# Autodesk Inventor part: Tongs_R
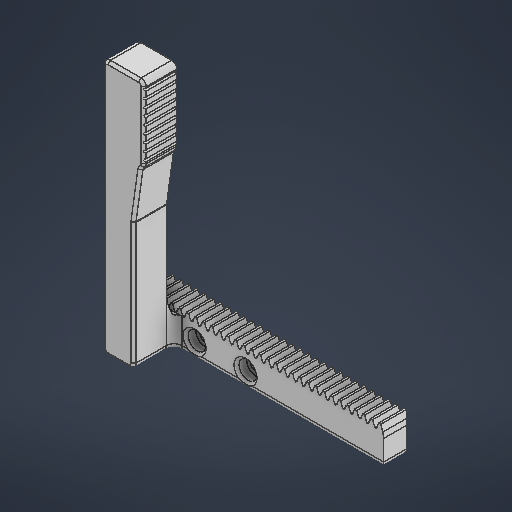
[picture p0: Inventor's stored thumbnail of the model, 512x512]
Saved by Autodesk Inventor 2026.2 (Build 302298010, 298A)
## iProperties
Company: Open CASCADE
Created: 2026-05
Part Number: Tongs_R
Material: 일반
Description: Open CASCADE Model
Document SubType Name: Modeling
Designer: work
Authority: Unknown
Density: 1 g/cm^3
Appearance: 기본값
Sending System: Open CASCADE 7.8
Preprocessor: Open CASCADE STEP processor 7.8
Title: Open CASCADE Shape Model
Author: Author
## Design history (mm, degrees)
feature "기준1"
sketch "스케치1"
  geometry: L1 (0.33, 2)-(1.149, 4.25) reference; L2 (0, 0)-(0.33, 2) reference; L3 (94.248, 0)-(0, 0) reference; L4 (93.917, 2)-(94.248, 0) reference; L5 (93.098, 4.25)-(93.917, 2) reference; L6 (92.256, 4.25)-(93.098, 4.25) reference; L7 (91.437, 2)-(92.256, 4.25) reference; L8 (90.776, 2)-(91.437, 2) reference; L9 (89.957, 4.25)-(90.776, 2) reference; L10 (89.114, 4.25)-(89.957, 4.25) reference; L11 (88.295, 2)-(89.114, 4.25) reference; L12 (87.634, 2)-(88.295, 2) reference; L13 (86.815, 4.25)-(87.634, 2) reference; L14 (85.972, 4.25)-(86.815, 4.25) reference; L15 (85.153, 2)-(85.972, 4.25) reference; L16 (84.493, 2)-(85.153, 2) reference; L17 (83.674, 4.25)-(84.493, 2) reference; L18 (82.831, 4.25)-(83.674, 4.25) reference; L19 (82.012, 2)-(82.831, 4.25) reference; L20 (81.351, 2)-(82.012, 2) reference; L21 (80.532, 4.25)-(81.351, 2) reference; L22 (79.689, 4.25)-(80.532, 4.25) reference; L23 (78.87, 2)-(79.689, 4.25) reference; L24 (78.209, 2)-(78.87, 2) reference; L25 (77.39, 4.25)-(78.209, 2) reference; L26 (76.548, 4.25)-(77.39, 4.25) reference; L27 (75.729, 2)-(76.548, 4.25) reference; L28 (75.068, 2)-(75.729, 2) reference; L29 (74.249, 4.25)-(75.068, 2) reference; L30 (73.406, 4.25)-(74.249, 4.25) reference; L31 (72.587, 2)-(73.406, 4.25) reference; L32 (71.926, 2)-(72.587, 2) reference; L33 (71.107, 4.25)-(71.926, 2) reference; L34 (70.264, 4.25)-(71.107, 4.25) reference; L35 (69.445, 2)-(70.264, 4.25) reference; L36 (68.785, 2)-(69.445, 2) reference; L37 (67.966, 4.25)-(68.785, 2) reference; L38 (67.123, 4.25)-(67.966, 4.25) reference; L39 (66.304, 2)-(67.123, 4.25) reference; L40 (65.643, 2)-(66.304, 2) reference; L41 (64.824, 4.25)-(65.643, 2) reference; L42 (63.981, 4.25)-(64.824, 4.25) reference; L43 (63.162, 2)-(63.981, 4.25) reference; L44 (62.501, 2)-(63.162, 2) reference; L45 (61.682, 4.25)-(62.501, 2) reference; L46 (60.84, 4.25)-(61.682, 4.25) reference; L47 (60.021, 2)-(60.84, 4.25) reference; L48 (59.36, 2)-(60.021, 2) reference; L49 (58.541, 4.25)-(59.36, 2) reference; L50 (57.698, 4.25)-(58.541, 4.25) reference; L51 (56.879, 2)-(57.698, 4.25) reference; L52 (56.218, 2)-(56.879, 2) reference; L53 (55.399, 4.25)-(56.218, 2) reference; L54 (54.556, 4.25)-(55.399, 4.25) reference; L55 (53.738, 2)-(54.556, 4.25) reference; L56 (53.077, 2)-(53.738, 2) reference; L57 (52.258, 4.25)-(53.077, 2) reference; L58 (51.415, 4.25)-(52.258, 4.25) reference; L59 (50.596, 2)-(51.415, 4.25) reference; L60 (49.935, 2)-(50.596, 2) reference; L61 (49.116, 4.25)-(49.935, 2) reference; L62 (48.273, 4.25)-(49.116, 4.25) reference; L63 (47.454, 2)-(48.273, 4.25) reference; L64 (46.793, 2)-(47.454, 2) reference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; 1 further point
  constraints: 8 end point, 2 parallel, 1 horizontal, 1 perpendicular, 1 point on line
  dimensions: "d0" = 10 distance of L123.end L124.end
extrude "돌출1" join sketch "스케치1" stored distance "d1" = 10; taper "d2" = 0 deg
sketch "스케치2"
  geometry: L1 (0.33, 12)-(1.149, 14.25) reference; L2 (0, 10)-(0.33, 12) reference; L3 (0, 10)-(0, 0) reference; L4 (0, 0)-(94.248, 0) reference; L5 (94.248, 0)-(94.248, 10) reference; L6 (93.917, 12)-(94.248, 10) reference; L7 (93.098, 14.25)-(93.917, 12) reference; L8 (92.256, 14.25)-(93.098, 14.25) reference; L9 (91.437, 12)-(92.256, 14.25) reference; L10 (90.776, 12)-(91.437, 12) reference; L11 (89.957, 14.25)-(90.776, 12) reference; L12 (89.114, 14.25)-(89.957, 14.25) reference; L13 (88.295, 12)-(89.114, 14.25) reference; L14 (87.634, 12)-(88.295, 12) reference; L15 (86.815, 14.25)-(87.634, 12) reference; L16 (85.972, 14.25)-(86.815, 14.25) reference; L17 (85.153, 12)-(85.972, 14.25) reference; L18 (84.493, 12)-(85.153, 12) reference; L19 (83.674, 14.25)-(84.493, 12) reference; L20 (82.831, 14.25)-(83.674, 14.25) reference; L21 (82.012, 12)-(82.831, 14.25) reference; L22 (81.351, 12)-(82.012, 12) reference; L23 (80.532, 14.25)-(81.351, 12) reference; L24 (79.689, 14.25)-(80.532, 14.25) reference; L25 (78.87, 12)-(79.689, 14.25) reference; L26 (78.209, 12)-(78.87, 12) reference; L27 (77.39, 14.25)-(78.209, 12) reference; L28 (76.548, 14.25)-(77.39, 14.25) reference; L29 (75.729, 12)-(76.548, 14.25) reference; L30 (75.068, 12)-(75.729, 12) reference; L31 (74.249, 14.25)-(75.068, 12) reference; L32 (73.406, 14.25)-(74.249, 14.25) reference; L33 (72.587, 12)-(73.406, 14.25) reference; L34 (71.926, 12)-(72.587, 12) reference; L35 (71.107, 14.25)-(71.926, 12) reference; L36 (70.264, 14.25)-(71.107, 14.25) reference; L37 (69.445, 12)-(70.264, 14.25) reference; L38 (68.785, 12)-(69.445, 12) reference; L39 (67.966, 14.25)-(68.785, 12) reference; L40 (67.123, 14.25)-(67.966, 14.25) reference; L41 (66.304, 12)-(67.123, 14.25) reference; L42 (65.643, 12)-(66.304, 12) reference; L43 (64.824, 14.25)-(65.643, 12) reference; L44 (63.981, 14.25)-(64.824, 14.25) reference; L45 (63.162, 12)-(63.981, 14.25) reference; L46 (62.501, 12)-(63.162, 12) reference; L47 (61.682, 14.25)-(62.501, 12) reference; L48 (60.84, 14.25)-(61.682, 14.25) reference; L49 (60.021, 12)-(60.84, 14.25) reference; L50 (59.36, 12)-(60.021, 12) reference; L51 (58.541, 14.25)-(59.36, 12) reference; L52 (57.698, 14.25)-(58.541, 14.25) reference; L53 (56.879, 12)-(57.698, 14.25) reference; L54 (56.218, 12)-(56.879, 12) reference; L55 (55.399, 14.25)-(56.218, 12) reference; L56 (54.556, 14.25)-(55.399, 14.25) reference; L57 (53.738, 12)-(54.556, 14.25) reference; L58 (53.077, 12)-(53.738, 12) reference; L59 (52.258, 14.25)-(53.077, 12) reference; L60 (51.415, 14.25)-(52.258, 14.25) reference; L61 (50.596, 12)-(51.415, 14.25) reference; L62 (49.935, 12)-(50.596, 12) reference; L63 (49.116, 14.25)-(49.935, 12) reference; L64 (48.273, 14.25)-(49.116, 14.25) reference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; C1 r 2 at (40, 5.688); C2 r 2 at (20, 5.688); 4 further points
  constraints: 8 end point, 5 point on line, 4 perpendicular, 3 midpoint, 2 centre point, 1 horizontal
  dimensions: "d4" = 0.5625 distance of L126.end point (47.124, 13.688); "d5" = 8 distance of point (47.124, 5.688) point (47.124, 13.688); "d6" = 4 diameter of C1; "d7" = 4 diameter of C2; "d8" = 20 distance of C1.centre C2.centre; "d36" = 20 horizontal distance of point (0, 5) C2.centre
extrude "돌출2" cut sketch "스케치2" extent not by distance; stored distance "d10" = 0; taper "d11" = 0 deg
sketch "스케치3"
  geometry: L1 (0, 0)-(94.248, 0) reference; L2 (0, 0)-(12, 0); L3 (12, 0)-(12, 100); L4 (12, 100)-(0, 100); L5 (12, 100)-(16, 100); L6 (16, 70)-(12, 70); L7 (12, 70)-(12, 100); L8 (16, 97)-(0, 97); L9 (12, 70)-(12, 0); C1 r 0.5 at (0, 97); C2 r 0.5 at (16, 97); C3 r 0.5 at (16, 94); C4 r 0.5 at (0, 94); C5 r 0.5 at (16, 91); C6 r 0.5 at (0, 91); C7 r 0.5 at (16, 88); C8 r 0.5 at (0, 88); C9 r 0.5 at (16, 85); C10 r 0.5 at (0, 85); C11 r 0.5 at (16, 82); C12 r 0.5 at (0, 82); C13 r 0.5 at (16, 79); C14 r 0.5 at (0, 79); C15 r 0.5 at (16, 76); C16 r 0.5 at (0, 76); C17 r 0.5 at (16, 73); C18 r 0.5 at (0, 73); 38 further points
  constraints: 18 centre point, 16 end point, 16 equal radius, 16 vertical alignment, 4 horizontal, 3 vertical, 2 parallel, 1 perpendicular, 8 other
  dimensions: "d12" = 12 distance of L3.end L4.end; "d13" = 100 distance between parallel lines of L1 L4; "d14" = 30 distance of L5.end L6.start; "d15" = 4 distance of L6.start L6.end; "d16" = 1 diameter of C1; "d17" = 1 diameter of C2; "d18" = 3 distance between parallel lines of L4 L8; "d21" = 3 distance of L8.start C3.centre
extrude "돌출3" join sketch "스케치3" distance "d26" = 16; taper "d27" = 0 deg
chamfer "모따기1" distance "d28" = 20; stored, may be unused: second distance "d29" = 2, angle "d30" = 171.887 deg
sketch "스케치4"
  geometry: L1 (0, 10)-(0, 0) reference; L2 (0, 0)-(26, 0) reference; L3 (26, 72.5)-(26, 0) reference; L4 (10, 72.5)-(26, 72.5) reference; L5 (10, 72.5)-(10, 10) reference; L6 (0, 10)-(10, 10) reference; L7 (26, 50)-(10, 10) reference; L8 (13, 20)-(13, 100); L9 (10, 100)-(26, 100) reference; L10 (10, 72.5)-(13, 72.5); L11 (13, 72.5)-(13, 100); L12 (13, 100)-(10, 100); L13 (10, 100)-(10, 72.5); A1 r 18.167 centre (-5.167, 20) between (10, 10) and (13, 20); 3 further points
  constraints: 10 end point, 2 parallel, 2 perpendicular, 2 point on circle, 1 centre point, 1 horizontal, 1 midpoint, 1 point on line, 1 tangent
  dimensions: "d31" = 10 vertical distance of L5.end L8.start; "d32" = 3 horizontal distance of point (10, 41.25) L8.start
extrude "돌출4" cut sketch "스케치4" extent not by distance; stored distance "d33" = 0; taper "d34" = 0 deg
fillet "모깎기1" dims "d35" = 3
chamfer "모따기2" distance "d37" = 2; stored, may be unused: second distance "d38" = 2, angle "d39" = 45 deg
fillet "모깎기2" dims "d40" = 2
chamfer "모따기3" distance "d41" = 1; stored, may be unused: second distance "d42" = 2, angle "d43" = 45 deg
sketch "스케치6"
  geometry: C1 r 2 at (-74.248, 3.688) reference; C2 r 2 at (-54.248, 3.688) reference; 3 further points
  constraints: 2 coincident
hole "구멍1" sketch "스케치6" at (-74.248, 3.688), (-54.248, 3.688) diameter "d44" = 4; stored, may be unused: countersink angle "d48" = 90 deg, drill point angle "d50" = 118 deg; dims "d45" = 6, "d46" = 7, "d47" = 4, "d49" = 8
chamfer "모따기4" distance "d51" = 1; stored, may be unused: second distance "d52" = 2, angle "d53" = 45 deg
node "솔리드1"
node "투영된 루프1"
node "투영된 루프2"
node "스케치 - 직사각형 패턴1" dims "d21" = 3, "d24" = 10
node "투영된 루프3"
feature "A9D066F2-1C7D-4E18-AEED-F7BC21143FA4" dims "d44" = 4, "d45" = 6, "d46" = 7, "d47" = 4, "d48" = 90 deg, "d49" = 8, "d50" = 118 deg
